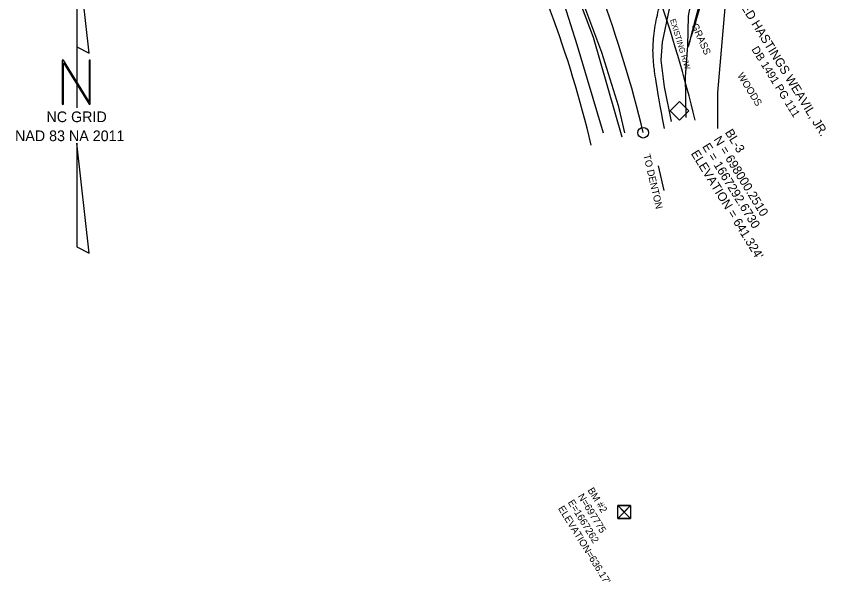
# Model space of a CAD drawing. Extents: x 1666477 to 1667385, y 697735 to 699095.
# Drawn here: x 1666919.8 to 1667374.9, y 697735.5 to 698053.6 of the extents above; entities that cross this region are included whole.
import ezdxf

# ---------------------------------------------------------------- set-up
doc = ezdxf.new("R2010")
doc.units = 0
for name, color, linetype in [('CTL Bench Mark CELL', 7, 'Continuous'), ('CTL Bench Mark Text', 7, 'Continuous'), ('CTL North Arrow NAD 83 NA 2011 CELL', 7, 'Continuous'), ('CTL Supplemental Horizontal and Vertical Text', 7, 'Continuous'), ('Exist Horizontal Alignment', 7, 'Continuous'), ('Exist Horizontal Alignment Point', 7, 'Continuous'), ('Exist Hydro Swamp or Marsh', 7, 'Continuous'), ('Exist Property Deed Book Text', 7, 'Continuous'), ('Exist Property Owner Text', 7, 'Continuous'), ('Exist Right of Way Line', 7, 'Continuous'), ('Exist Right of Way Line Text', 7, 'Continuous'), ('Exist Roads EOP', 7, 'Continuous'), ('Exist Roads EOP Leader', 7, 'Continuous'), ('Exist Roads EOP Text', 7, 'Continuous'), ('Exist Utilities Telephone UG Cable SUE LOS C', 7, 'Continuous'), ('Exist Utilities Water UG Line SUE LOS C', 7, 'Continuous'), ('Exist Vegetation Woods Line', 7, 'Continuous'), ('Exist Vegetation Woods Line Text', 7, 'Continuous')]:
    doc.layers.add(name, color=color, linetype=linetype)

msp = doc.modelspace()

# ---------------------------------------------------------------- linework, layer by layer
at = {"layer": 'CTL Bench Mark CELL'}
msp.add_line((1667261.65, 697774.74), (1667261.65, 697774.74), dxfattribs=at)
msp.add_line((1667261.65, 697774.74), (1667261.65, 697774.74), dxfattribs=at)
msp.add_lwpolyline([(1667258.05, 697778.33), (1667265.23, 697778.33), (1667265.23, 697771.14), (1667258.05, 697771.14)], close=True, dxfattribs=at)
msp.add_lwpolyline([(1667258.05, 697778.33), (1667265.23, 697778.33), (1667265.23, 697771.14), (1667258.05, 697771.14)], close=True, dxfattribs=at)
for points in [[(1667265.23, 697778.33), (1667258.05, 697771.14), (1667261.64, 697774.73), (1667265.23, 697771.14), (1667258.05, 697778.33)], [(1667261.64, 697774.73), (1667265.23, 697778.33), (1667258.05, 697778.33), (1667261.64, 697774.73)], [(1667265.23, 697778.33), (1667258.05, 697771.14), (1667261.64, 697774.73), (1667265.23, 697771.14), (1667258.05, 697778.33)], [(1667261.64, 697774.73), (1667265.23, 697778.33), (1667258.05, 697778.33), (1667261.64, 697774.73)], [(1667261.64, 697774.73), (1667258.05, 697771.14), (1667265.23, 697771.14), (1667261.64, 697774.73)], [(1667261.64, 697774.73), (1667258.05, 697771.14), (1667265.23, 697771.14), (1667261.64, 697774.73)]]:
    msp.add_lwpolyline(points, dxfattribs=at)
at = {"layer": 'CTL North Arrow NAD 83 NA 2011 CELL'}
msp.add_line((1666954.09, 698007.32), (1666954.09, 698007.32), dxfattribs=at)
for points in [[(1666953.94, 698094.6), (1666953.94, 698036.28), (1666960.81, 698032.84)], [(1666945.71, 698004.05), (1666946.4, 698004.05), (1666946.4, 698027.38), (1666960.81, 698004.05), (1666961.5, 698004.05), (1666961.5, 698028.74), (1666960.81, 698028.74), (1666960.81, 698005.42), (1666946.4, 698028.74), (1666945.71, 698028.74)], [(1666953.94, 697923.77), (1666960.81, 697920.35), (1666953.94, 697982.09)]]:
    msp.add_lwpolyline(points, close=True, dxfattribs=at)
msp.add_lwpolyline([(1666953.94, 698036.28), (1666953.94, 698001.98)], dxfattribs=at)
at = {"layer": 'Exist Horizontal Alignment'}
msp.add_arc((1666615.77, 697831.24), 675, 13.43431, 27.44148, dxfattribs=at)
at = {"layer": 'Exist Horizontal Alignment Point'}
msp.add_circle((1667272.3, 697988.06), 3, dxfattribs=at)
at = {"layer": 'Exist Hydro Swamp or Marsh'}
msp.add_line((1667292.67, 698000.25), (1667292.67, 698000.25), dxfattribs=at)
msp.add_lwpolyline([(1667287.46, 698000.27), (1667292.7, 698005.51), (1667297.95, 698000.26), (1667292.71, 697995.02)], close=True, dxfattribs=at)
at = {"layer": 'Exist Right of Way Line'}
for radius, end in [(645, 27.44148), (705, 19.57757)]:
    msp.add_arc((1666615.77, 697831.24), radius, 13.43431, end, dxfattribs=at)
at = {"layer": 'Exist Roads EOP'}
msp.add_lwpolyline([(1667099.22, 698316.6), (1667108.08, 698301.69), (1667134.43, 698259.92), (1667160.04, 698217.25), (1667184.17, 698175.17), (1667207.18, 698131.15), (1667226.77, 698087.83), (1667244.1, 698041.72), (1667260.38, 697985.64)], dxfattribs=at)
msp.add_open_spline([(1667284.22, 697990.49), (1667279.41, 698016.63), (1667277.99, 698027.32), (1667277.58, 698036.36), (1667278.87, 698048.28), (1667281.54, 698060.19), (1667285.55, 698070.41), (1667289.29, 698076.41), (1667296.2, 698085.95), (1667305.81, 698097.11), (1667318.05, 698105.13), (1667284.22, 697990.49), (1667318.05, 698105.13)], degree=3, dxfattribs=at)
at = {"layer": 'Exist Roads EOP Leader'}
msp.add_lwpolyline([(1667284.1, 697955.5), (1667280.81, 697969.42)], dxfattribs=at)
at = {"layer": 'Exist Utilities Telephone UG Cable SUE LOS C'}
for points in [[(1667099.78, 698295.23), (1667104.58, 698295.06), (1667105.28, 698294.86), (1667109.75, 698296.75), (1667112.75, 698295.93), (1667122.15, 698280.53), (1667140.12, 698252.86), (1667152.02, 698232.35), (1667172.25, 698197.12), (1667186.57, 698171.02), (1667200.61, 698146.58), (1667217.56, 698112.49), (1667228.97, 698085.98), (1667238.74, 698060.32), (1667248.79, 698033.29), (1667258.23, 698003.41), (1667261.8, 697987.89)], [(1667101.04, 698287.86), (1667103.39, 698288.27), (1667105.84, 698287.03), (1667116.85, 698268.47), (1667135.07, 698238.76), (1667146.02, 698219.82), (1667159.08, 698199.08), (1667172.89, 698177.9), (1667184.29, 698155.76), (1667187.31, 698147.32), (1667203.23, 698116.85), (1667218.01, 698085.89), (1667227.81, 698060.07), (1667235.08, 698037.61), (1667249.81, 697987.88)], [(1667322.35, 698100.65), (1667313.01, 698094.16), (1667307.72, 698087.97), (1667302, 698077.93), (1667297.52, 698053.65), (1667297.26, 698036.87), (1667295.84, 698019.41), (1667296.32, 697996.67)]]:
    msp.add_lwpolyline(points, dxfattribs=at)
at = {"layer": 'Exist Utilities Water UG Line SUE LOS C'}
msp.add_lwpolyline([(1667288.19, 697994.35), (1667284.24, 698013.78), (1667282.49, 698028.84), (1667283.11, 698038.91), (1667287.13, 698057.73), (1667296.73, 698079.36)], dxfattribs=at)
at = {"layer": 'Exist Vegetation Woods Line'}
msp.add_lwpolyline([(1667314.2, 697990.44), (1667314.3, 698010.65), (1667320.56, 698084.51), (1667329.43, 698091.93), (1667347.07, 698105.04)], dxfattribs=at)

# ---------------------------------------------------------------- texts
at = {"layer": 'CTL Bench Mark Text'}
for s, p in [('BM #2', (1667240.86, 697787.01)), ('E=1667262', (1667229.8, 697780.18)), ('N=697775', (1667235.33, 697783.59)), ("ELEVATION=636.17'", (1667224.27, 697776.76))]:
    msp.add_text(s, height=4, rotation=301.6959, dxfattribs=at).set_placement(p)
at = {"layer": 'CTL North Arrow NAD 83 NA 2011 CELL'}
for s, p in [('NC GRID', (1666936.86, 697993.98)), ('NAD 83 NA 2011', (1666919.17, 697983.3))]:
    msp.add_text(s, height=6, dxfattribs=at).set_placement(p)
at = {"layer": 'CTL Supplemental Horizontal and Vertical Text'}
for s, p in [('BL-3', (1667318.07, 697988.18)), ('N = 698000.2510', (1667311.69, 697984.24)), ('E = 1667292.6730', (1667305.31, 697980.3)), ("ELEVATION = 641.324'", (1667298.92, 697976.36))]:
    msp.add_text(s, height=5, rotation=301.6959, dxfattribs=at).set_placement(p)
at = {"layer": 'Exist Property Deed Book Text'}
msp.add_text('DB 1491 PG 111', height=4.5, rotation=301.6959, dxfattribs=at).set_placement((1667332.99, 698034.94))
at = {"layer": 'Exist Property Owner Text'}
msp.add_text('NED HASTINGS WEAVIL, JR.', height=5, rotation=301.6959, dxfattribs=at).set_placement((1667324.55, 698062.9))
at = {"layer": 'Exist Right of Way Line Text'}
msp.add_text('EXISTING R/W', height=3.2, rotation=286.8714, dxfattribs=at).set_placement((1667287.34, 698051.53))
at = {"layer": 'Exist Roads EOP Text'}
msp.add_text('TO DENTON', height=4, rotation=283.2659, dxfattribs=at).set_placement((1667272.31, 697975.48))
at = {"layer": 'Exist Vegetation Woods Line Text'}
for s, rotation, p in [('GRASS', 294.0773, (1667299.26, 698048.47)), ('WOODS', 301.6959, (1667325.06, 698020.26))]:
    msp.add_text(s, height=4, rotation=rotation, dxfattribs=at).set_placement(p)

doc.saveas('drawing.dxf')
